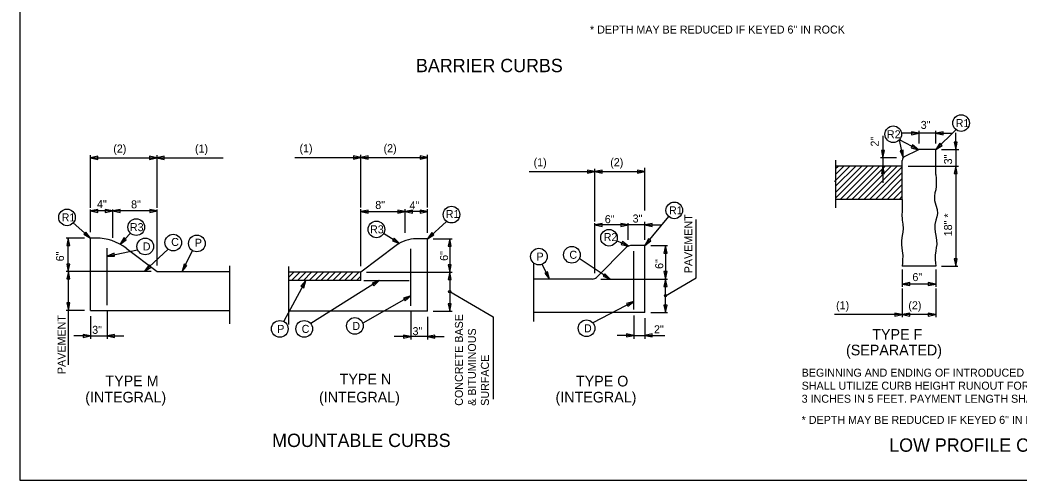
# Model space of a CAD drawing. Extents: x -439.1 to -407.9, y -458.1 to -436.2.
# Drawn here: x -439.11 to -420.39, y -458.05 to -449.44 of the extents above; entities that cross this region are included whole.
import ezdxf

# ---------------------------------------------------------------- set-up
doc = ezdxf.new("R2010")
doc.units = 0
for name, color, linetype in [('Draft_Named_Boundary', 7, 'Continuous'), ('Level 4', 7, 'Continuous'), ('Level 45', 7, 'Continuous')]:
    doc.layers.add(name, color=color, linetype=linetype)

msp = doc.modelspace()

# ---------------------------------------------------------------- linework, layer by layer
at = {"layer": 'Draft_Named_Boundary'}
msp.add_lwpolyline([(-439.109, -458.051), (-407.859, -458.051), (-407.859, -437.676), (-439.109, -437.676)], close=True, dxfattribs=at)
at = {"layer": 'Level 4'}
for p, q in [((-422.94, -451.607), (-422.94, -452.016)), ((-422.264, -451.556), (-422.577, -451.556)), ((-422.264, -451.751), (-422.264, -451.515)), ((-421.952, -451.556), (-422.264, -451.556)), ((-421.952, -451.751), (-421.952, -451.515)), ((-421.952, -451.556), (-421.639, -451.556)), ((-421.95, -451.86), (-421.573, -451.491)), ((-421.576, -451.86), (-421.576, -451.548)), ((-422.274, -451.866), (-422.632, -451.683)), ((-422.562, -452.014), (-422.632, -451.683)), ((-421.952, -451.86), (-422.246, -451.86)), ((-421.952, -452.328), (-421.952, -451.86)), ((-421.842, -451.86), (-421.521, -451.86)), ((-421.576, -451.853), (-421.576, -451.86)), ((-421.576, -451.86), (-421.576, -452.173)), ((-437.789, -452.953), (-437.789, -451.967)), ((-437.789, -452.018), (-435.305, -452.018)), ((-436.539, -452.953), (-436.539, -451.967)), ((-433.957, -452.012), (-431.474, -452.012)), ((-432.724, -452.947), (-432.724, -451.961)), ((-431.474, -452.947), (-431.474, -451.961)), ((-422.686, -452.016), (-422.986, -452.016)), ((-422.94, -452.016), (-422.94, -452.173)), ((-422.534, -451.995), (-422.281, -451.868)), ((-428.338, -453.209), (-428.338, -452.224)), ((-427.4, -453.002), (-427.4, -452.202)), ((-423.85, -452.463), (-423.559, -452.173)), ((-423.827, -452.772), (-423.228, -452.173)), ((-423.827, -452.551), (-423.449, -452.173)), ((-423.827, -452.219), (-423.78, -452.173)), ((-423.826, -452.951), (-423.826, -452.061)), ((-422.577, -452.172), (-423.826, -452.172)), ((-423.826, -452.661), (-423.338, -452.173)), ((-423.814, -452.317), (-423.67, -452.173)), ((-423.742, -452.798), (-423.117, -452.173)), ((-423.632, -452.798), (-423.007, -452.173)), ((-423.521, -452.798), (-422.896, -452.173)), ((-423.411, -452.798), (-422.786, -452.173)), ((-423.3, -452.798), (-422.675, -452.173)), ((-423.19, -452.798), (-422.577, -452.185)), ((-422.94, -452.173), (-422.94, -452.485)), ((-422.577, -452.797), (-422.577, -452.065)), ((-422.467, -452.173), (-421.524, -452.173)), ((-422.467, -452.173), (-421.53, -452.173)), ((-421.576, -452.173), (-421.576, -452.485)), ((-421.576, -452.173), (-421.576, -454.048)), ((-429.571, -452.274), (-427.4, -452.274)), ((-423.079, -452.798), (-422.577, -452.295)), ((-422.969, -452.798), (-422.577, -452.406)), ((-422.858, -452.798), (-422.577, -452.516)), ((-422.748, -452.798), (-422.577, -452.627)), ((-422.637, -452.798), (-422.577, -452.737)), ((-437.789, -453.41), (-437.789, -452.983)), ((-437.372, -453.515), (-437.372, -452.983)), ((-436.539, -454.035), (-436.539, -452.983)), ((-432.724, -454.049), (-432.724, -452.977)), ((-431.891, -453.424), (-431.891, -452.977)), ((-431.474, -453.424), (-431.474, -452.977)), ((-422.577, -452.797), (-423.826, -452.797)), ((-437.372, -453.012), (-437.789, -453.012)), ((-436.539, -453.012), (-437.372, -453.012)), ((-432.724, -453.025), (-431.891, -453.025)), ((-431.474, -453.025), (-431.891, -453.025)), ((-427.4, -453.662), (-426.954, -453.117)), ((-437.789, -453.52), (-438.111, -453.235)), ((-431.474, -453.533), (-431.119, -453.207)), ((-428.338, -454.178), (-428.338, -453.24)), ((-427.713, -453.275), (-428.338, -453.275)), ((-427.713, -453.275), (-428.025, -453.275)), ((-427.713, -453.553), (-427.713, -453.24)), ((-427.4, -453.275), (-427.713, -453.275)), ((-427.4, -453.553), (-427.4, -453.218)), ((-427.4, -453.275), (-427.088, -453.275)), ((-427.366, -453.275), (-427.4, -453.275)), ((-426.437, -454.267), (-426.437, -453.175)), ((-437.898, -453.52), (-438.244, -453.52)), ((-438.205, -454.145), (-438.205, -453.52)), ((-437.789, -454.874), (-437.789, -453.519)), ((-437.789, -453.519), (-437.685, -453.519)), ((-437.235, -453.634), (-437.04, -453.427)), ((-431.999, -453.619), (-432.295, -453.433)), ((-431.474, -453.533), (-431.683, -453.533)), ((-431.474, -454.888), (-431.474, -453.533)), ((-431.365, -453.533), (-431.009, -453.533)), ((-431.058, -453.533), (-431.058, -454.158)), ((-437.476, -454.776), (-437.476, -453.708)), ((-437.122, -453.707), (-436.539, -454.144)), ((-436.773, -454.138), (-436.333, -453.728)), ((-432.058, -453.658), (-432.724, -454.158)), ((-431.786, -454.789), (-431.786, -453.722)), ((-427.744, -453.693), (-428.308, -454.257)), ((-427.715, -453.672), (-427.925, -453.575)), ((-427.4, -453.662), (-427.67, -453.662)), ((-427.4, -454.912), (-427.4, -453.662)), ((-427.291, -453.662), (-426.976, -453.662)), ((-427.014, -453.662), (-427.014, -454.287)), ((-437.476, -453.862), (-436.904, -453.743)), ((-436.07, -454.145), (-435.875, -453.755)), ((-428.052, -454.287), (-428.629, -453.905)), ((-427.609, -454.86), (-427.609, -453.764)), ((-435.176, -455.125), (-435.176, -454.04)), ((-434.069, -455.138), (-434.069, -454.053)), ((-429.484, -455.084), (-429.484, -453.993)), ((-429.186, -454.287), (-429.325, -454.012)), ((-421.952, -454.047), (-422.577, -454.047)), ((-421.842, -454.048), (-421.535, -454.048)), ((-436.648, -454.145), (-438.244, -454.145)), ((-438.202, -454.874), (-438.202, -454.145)), ((-436.539, -454.144), (-435.185, -454.144)), ((-432.724, -454.158), (-434.078, -454.158)), ((-434.078, -454.261), (-433.975, -454.158)), ((-434.021, -454.315), (-433.865, -454.158)), ((-433.911, -454.315), (-433.754, -454.158)), ((-433.8, -454.315), (-433.644, -454.158)), ((-433.69, -454.315), (-433.534, -454.158)), ((-433.579, -454.315), (-433.423, -454.158)), ((-433.469, -454.315), (-433.313, -454.158)), ((-433.358, -454.315), (-433.202, -454.158)), ((-433.248, -454.315), (-433.092, -454.158)), ((-433.137, -454.315), (-432.981, -454.158)), ((-433.027, -454.315), (-432.871, -454.158)), ((-432.916, -454.315), (-432.76, -454.158)), ((-432.806, -454.315), (-432.724, -454.233)), ((-432.724, -454.314), (-432.724, -454.158)), ((-432.615, -454.158), (-431.009, -454.158)), ((-431.058, -454.158), (-431.058, -454.887)), ((-428.381, -454.287), (-429.484, -454.287)), ((-428.229, -454.287), (-426.976, -454.287)), ((-427.014, -454.6), (-426.437, -454.267)), ((-427.014, -454.912), (-427.014, -454.287)), ((-422.577, -454.109), (-422.577, -454.432)), ((-421.952, -454.109), (-421.952, -454.432)), ((-433.752, -454.315), (-434.168, -455.077)), ((-432.724, -454.314), (-434.078, -454.314)), ((-432.381, -454.315), (-433.66, -455.122)), ((-432.664, -454.314), (-431.814, -454.314)), ((-421.952, -454.382), (-422.577, -454.382)), ((-422.577, -454.462), (-422.577, -455.003)), ((-421.952, -454.462), (-421.952, -455.003)), ((-431.787, -454.601), (-432.683, -455.111)), ((-431.058, -454.523), (-430.243, -454.994)), ((-427.609, -454.706), (-428.375, -455.109)), ((-437.898, -454.874), (-438.244, -454.874)), ((-438.202, -455.894), (-438.202, -454.874)), ((-437.789, -454.874), (-435.185, -454.874)), ((-437.789, -454.983), (-437.789, -455.408)), ((-437.476, -454.886), (-437.476, -455.408)), ((-431.474, -454.888), (-434.078, -454.888)), ((-431.787, -454.899), (-431.787, -455.419)), ((-431.474, -454.997), (-431.474, -455.419)), ((-431.365, -454.887), (-431.009, -454.887)), ((-430.243, -454.994), (-430.243, -456.539)), ((-427.4, -454.912), (-429.484, -454.912)), ((-427.609, -454.97), (-427.609, -455.408)), ((-427.4, -455.022), (-427.4, -455.408)), ((-427.291, -454.912), (-426.976, -454.912)), ((-421.952, -454.953), (-423.847, -454.953)), ((-437.789, -455.353), (-438.101, -455.353)), ((-437.789, -455.353), (-437.476, -455.353)), ((-437.476, -455.353), (-437.164, -455.353)), ((-431.787, -455.366), (-432.099, -455.366)), ((-431.474, -455.366), (-431.787, -455.366)), ((-431.474, -455.366), (-431.162, -455.366)), ((-427.609, -455.344), (-427.921, -455.344)), ((-427.609, -455.344), (-427.4, -455.344)), ((-427.4, -455.344), (-427.088, -455.344)), ((-427.4, -455.344), (-427.028, -455.344))]:
    msp.add_line(p, q, dxfattribs=at)
for points in [[(-422.403, -451.585), (-422.264, -451.556), (-422.403, -451.528)], [(-421.814, -451.528), (-421.952, -451.556), (-421.814, -451.585)], [(-422.41, -451.828), (-422.274, -451.866), (-422.384, -451.777)], [(-422.41, -451.828), (-422.274, -451.866), (-422.384, -451.777)], [(-421.872, -451.743), (-421.95, -451.86), (-421.831, -451.784)], [(-421.872, -451.743), (-421.95, -451.86), (-421.831, -451.784)], [(-421.605, -451.722), (-421.576, -451.86), (-421.548, -451.722)], [(-437.65, -451.989), (-437.789, -452.018), (-437.65, -452.047)], [(-436.685, -452.047), (-436.547, -452.018), (-436.685, -451.989)], [(-436.409, -451.989), (-436.547, -452.018), (-436.409, -452.047)], [(-432.862, -452.041), (-432.724, -452.012), (-432.862, -451.983)], [(-432.586, -451.983), (-432.724, -452.012), (-432.586, -452.041)], [(-431.613, -452.041), (-431.474, -452.012), (-431.613, -451.983)], [(-422.968, -451.878), (-422.94, -452.016), (-422.911, -451.878)], [(-422.618, -451.884), (-422.562, -452.014), (-422.562, -451.872)], [(-422.618, -451.884), (-422.562, -452.014), (-422.562, -451.872)], [(-422.911, -452.311), (-422.94, -452.173), (-422.968, -452.311)], [(-421.548, -452.311), (-421.576, -452.173), (-421.605, -452.311)], [(-428.476, -452.303), (-428.338, -452.274), (-428.476, -452.246)], [(-428.2, -452.246), (-428.338, -452.274), (-428.2, -452.303)], [(-427.539, -452.303), (-427.4, -452.274), (-427.539, -452.246)], [(-437.65, -452.983), (-437.789, -453.012), (-437.65, -453.041)], [(-437.51, -453.041), (-437.372, -453.012), (-437.51, -452.983)], [(-437.234, -452.983), (-437.372, -453.012), (-437.234, -453.041)], [(-436.677, -453.041), (-436.539, -453.012), (-436.677, -452.983)], [(-432.586, -452.997), (-432.724, -453.025), (-432.586, -453.054)], [(-432.029, -453.054), (-431.891, -453.025), (-432.029, -452.997)], [(-431.753, -452.997), (-431.891, -453.025), (-431.753, -453.054)], [(-431.613, -453.054), (-431.474, -453.025), (-431.613, -452.997)], [(-428.2, -453.246), (-428.338, -453.275), (-428.2, -453.304)], [(-427.851, -453.304), (-427.713, -453.275), (-427.851, -453.246)], [(-427.262, -453.246), (-427.4, -453.275), (-427.262, -453.304)], [(-438.176, -453.658), (-438.205, -453.52), (-438.234, -453.658)], [(-437.911, -453.45), (-437.789, -453.52), (-437.873, -453.407)], [(-437.911, -453.45), (-437.789, -453.52), (-437.873, -453.407)], [(-437.162, -453.514), (-437.235, -453.634), (-437.12, -453.553)], [(-437.162, -453.514), (-437.235, -453.634), (-437.12, -453.553)], [(-432.131, -453.57), (-431.999, -453.619), (-432.101, -453.521)], [(-432.131, -453.57), (-431.999, -453.619), (-432.101, -453.521)], [(-431.392, -453.419), (-431.474, -453.533), (-431.353, -453.461)], [(-431.392, -453.419), (-431.474, -453.533), (-431.353, -453.461)], [(-431.03, -453.672), (-431.058, -453.533), (-431.087, -453.672)], [(-427.335, -453.537), (-427.4, -453.662), (-427.291, -453.574)], [(-427.335, -453.537), (-427.4, -453.662), (-427.291, -453.574)], [(-427.847, -453.638), (-427.71, -453.67), (-427.823, -453.586)], [(-427.847, -453.638), (-427.71, -453.67), (-427.823, -453.586)], [(-426.985, -453.801), (-427.014, -453.662), (-427.043, -453.801)], [(-437.347, -453.806), (-437.476, -453.862), (-437.335, -453.862)], [(-437.347, -453.806), (-437.476, -453.862), (-437.335, -453.862)], [(-421.605, -453.909), (-421.576, -454.048), (-421.548, -453.909)], [(-438.234, -454.006), (-438.205, -454.145), (-438.176, -454.006)], [(-436.691, -454.023), (-436.773, -454.138), (-436.652, -454.065)], [(-436.691, -454.023), (-436.773, -454.138), (-436.652, -454.065)], [(-436.034, -454.008), (-436.07, -454.145), (-435.983, -454.034)], [(-436.034, -454.008), (-436.07, -454.145), (-435.983, -454.034)], [(-431.087, -454.02), (-431.058, -454.158), (-431.03, -454.02)], [(-438.174, -454.283), (-438.202, -454.145), (-438.231, -454.283)], [(-431.03, -454.297), (-431.058, -454.158), (-431.087, -454.297)], [(-429.274, -454.177), (-429.186, -454.287), (-429.223, -454.151)], [(-429.274, -454.177), (-429.186, -454.287), (-429.223, -454.151)], [(-428.183, -454.235), (-428.052, -454.287), (-428.151, -454.187)], [(-428.183, -454.235), (-428.052, -454.287), (-428.151, -454.187)], [(-427.043, -454.149), (-427.014, -454.287), (-426.985, -454.149)], [(-426.985, -454.426), (-427.014, -454.287), (-427.043, -454.426)], [(-433.793, -454.45), (-433.752, -454.315), (-433.844, -454.422)], [(-433.793, -454.45), (-433.752, -454.315), (-433.844, -454.422)], [(-432.482, -454.413), (-432.381, -454.315), (-432.513, -454.364)], [(-432.482, -454.413), (-432.381, -454.315), (-432.513, -454.364)], [(-422.439, -454.354), (-422.577, -454.382), (-422.439, -454.411)], [(-422.09, -454.411), (-421.952, -454.382), (-422.09, -454.354)], [(-431.893, -454.694), (-431.787, -454.601), (-431.921, -454.644)], [(-431.893, -454.694), (-431.787, -454.601), (-431.921, -454.644)], [(-438.231, -454.736), (-438.202, -454.874), (-438.174, -454.736)], [(-431.087, -454.749), (-431.058, -454.887), (-431.03, -454.749)], [(-427.718, -454.795), (-427.609, -454.706), (-427.745, -454.745)], [(-427.718, -454.795), (-427.609, -454.706), (-427.745, -454.745)], [(-427.043, -454.774), (-427.014, -454.912), (-426.985, -454.774)], [(-422.715, -454.982), (-422.577, -454.953), (-422.715, -454.924)], [(-422.439, -454.924), (-422.577, -454.953), (-422.439, -454.982)], [(-422.09, -454.982), (-421.952, -454.953), (-422.09, -454.924)], [(-437.927, -455.381), (-437.789, -455.353), (-437.927, -455.324)], [(-437.338, -455.324), (-437.476, -455.353), (-437.338, -455.381)], [(-431.925, -455.395), (-431.787, -455.366), (-431.925, -455.337)], [(-431.336, -455.337), (-431.474, -455.366), (-431.336, -455.395)], [(-427.747, -455.372), (-427.609, -455.344), (-427.747, -455.315)], [(-427.262, -455.315), (-427.4, -455.344), (-427.262, -455.372)]]:
    msp.add_lwpolyline(points, close=True, dxfattribs=at)
for points in [[(-421.952, -452.329), (-421.944, -452.405), (-421.942, -452.482), (-421.943, -452.549), (-421.952, -452.615), (-421.966, -452.674), (-421.977, -452.733), (-421.973, -452.817), (-421.952, -452.902), (-421.926, -452.983), (-421.917, -453.062), (-421.931, -453.125), (-421.952, -453.188), (-421.965, -453.264), (-421.966, -453.342), (-421.961, -453.408), (-421.952, -453.475), (-421.937, -453.557), (-421.931, -453.639), (-421.94, -453.7), (-421.952, -453.761), (-421.959, -453.843), (-421.959, -453.925), (-421.957, -453.986), (-421.952, -454.048)], [(-422.577, -452.798), (-422.578, -452.829), (-422.578, -452.861), (-422.577, -452.881), (-422.577, -452.902), (-422.581, -453.002), (-422.584, -453.101), (-422.582, -453.145), (-422.577, -453.188), (-422.568, -453.263), (-422.564, -453.338), (-422.568, -453.407), (-422.577, -453.475), (-422.591, -453.563), (-422.595, -453.65), (-422.587, -453.706), (-422.577, -453.761), (-422.57, -453.848), (-422.571, -453.935), (-422.573, -453.991), (-422.577, -454.048)]]:
    msp.add_lwpolyline(points, dxfattribs=at)
for centre, radius in [((-421.477, -451.367), 0.156), ((-422.747, -451.577), 0.156), ((-438.228, -453.133), 0.156), ((-431.024, -453.082), 0.156), ((-426.849, -453.001), 0.156), ((-436.93, -453.316), 0.156), ((-432.432, -453.357), 0.156), ((-428.073, -453.513), 0.156), ((-436.762, -453.677), 0.156), ((-436.237, -453.605), 0.156), ((-435.795, -453.621), 0.156), ((-429.385, -453.867), 0.156), ((-428.768, -453.833), 0.156), ((-431.058, -454.523), 0.0208), ((-427.014, -454.6), 0.0208), ((-432.834, -455.166), 0.156), ((-434.241, -455.221), 0.156), ((-433.784, -455.221), 0.156), ((-428.494, -455.21), 0.156)]:
    msp.add_circle(centre, radius, dxfattribs=at)
for centre, radius, start, end in [((-422.246, -451.938), 0.0781, 90, 116.5651), ((-422.499, -452.065), 0.0781, 116.565, 180), ((-437.684, -454.457), 0.937, 53.1301, 90), ((-431.683, -454.158), 0.625, 90, 126.8699), ((-427.67, -453.766), 0.104, 90, 134.9999), ((-428.381, -454.183), 0.104, 270, 315)]:
    msp.add_arc(centre, radius, start, end, dxfattribs=at)

# ---------------------------------------------------------------- texts
for s, height, p in [('BARRIER CURBS', 0.25, (-431.689, -450.414)), ('R1', 0.15, (-421.577, -451.442)), ('R2', 0.15, (-422.866, -451.652)), ('R1', 0.15, (-426.949, -453.076)), ('R1', 0.15, (-438.328, -453.208)), ('R1', 0.15, (-431.131, -453.145)), ('R3', 0.15, (-437.049, -453.391)), ('R3', 0.15, (-432.55, -453.432)), ('C', 0.15, (-436.276, -453.668)), ('P', 0.15, (-435.834, -453.683)), ('R2', 0.15, (-428.172, -453.576)), ('D', 0.15, (-436.809, -453.752)), ('P', 0.15, (-429.432, -453.942)), ('C', 0.15, (-428.815, -453.908)), ('P', 0.15, (-434.289, -455.296)), ('C', 0.15, (-433.832, -455.296)), ('D', 0.15, (-432.882, -455.241)), ('D', 0.15, (-428.542, -455.285)), ('TYPE F', 0.2, (-423.14, -455.424)), ('(SEPARATED)', 0.2, (-423.632, -455.717)), ('TYPE M', 0.2, (-437.508, -456.294)), ('TYPE N', 0.2, (-433.119, -456.261)), ('TYPE O', 0.2, (-428.692, -456.299)), ('(INTEGRAL)', 0.2, (-437.886, -456.599)), ('(INTEGRAL)', 0.2, (-433.506, -456.599)), ('(INTEGRAL)', 0.2, (-429.075, -456.599)), ('MOUNTABLE CURBS', 0.25, (-434.384, -457.433)), ('LOW PROFILE CURB', 0.25, (-422.822, -457.522))]:
    msp.add_text(s, height=height, dxfattribs=at).set_placement(p)
for s, p in [('PAVEMENT', (-426.511, -454.179)), ('PAVEMENT', (-438.256, -456.067)), ('CONCRETE BASE', (-430.81, -456.661)), ('& BITUMINOUS', (-430.566, -456.661)), ('SURFACE', (-430.323, -456.661))]:
    msp.add_text(s, height=0.15, rotation=90, dxfattribs=at).set_placement(p)
at = {"layer": 'Level 45'}
for s, p in [('* DEPTH MAY BE REDUCED IF KEYED 6" IN ROCK', (-428.429, -449.691)), ('3"', (-422.232, -451.476)), ('(2)', (-437.361, -451.919)), ('(1)', (-435.83, -451.919)), ('(1)', (-433.872, -451.913)), ('(2)', (-432.297, -451.913)), ('(1)', (-429.486, -452.175)), ('(2)', (-428.05, -452.175)), ('4"', (-437.666, -452.958)), ('8"', (-437.027, -452.964)), ('8"', (-432.452, -452.975)), ('4"', (-431.811, -452.983)), ('6"', (-428.152, -453.242)), ('3"', (-427.63, -453.229)), ('6"', (-422.388, -454.326)), ('(1)', (-423.818, -454.854)), ('(2)', (-422.464, -454.854)), ('3"', (-437.756, -455.314)), ('3"', (-431.754, -455.338)), ('2"', (-427.23, -455.304)), ('BEGINNING AND ENDING OF INTRODUCED LOW PROFILE CURB', (-424.463, -456.116)), ('SHALL UTILIZE CURB HEIGHT RUNOUT FORM O INCHES TO ', (-424.463, -456.36)), ('3 INCHES IN 5 FEET. PAYMENT LENGTH SHALL INCLUDE TAPERS.', (-424.463, -456.604)), ('* DEPTH MAY BE REDUCED IF KEYED 6" IN ROCK.', (-424.463, -457))]:
    msp.add_text(s, height=0.15, dxfattribs=at).set_placement(p)
for s, p in [('2"', (-423.019, -451.807)), ('3"', (-421.645, -452.14)), ('18" *', (-421.645, -453.488)), ('6"', (-438.284, -453.956)), ('6"', (-431.089, -453.947)), ('6"', (-427.057, -454.098))]:
    msp.add_text(s, height=0.15, rotation=90, dxfattribs=at).set_placement(p)

doc.saveas('drawing.dxf')
